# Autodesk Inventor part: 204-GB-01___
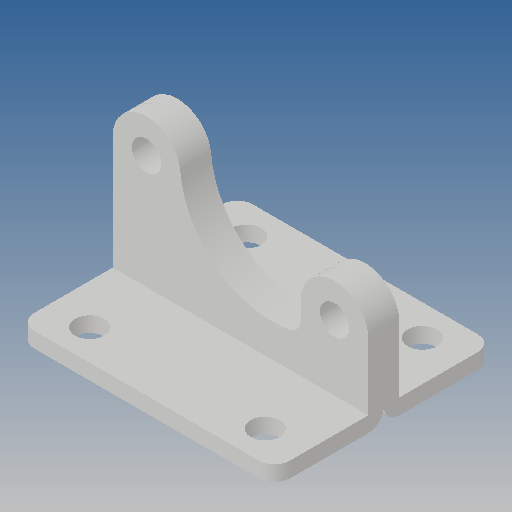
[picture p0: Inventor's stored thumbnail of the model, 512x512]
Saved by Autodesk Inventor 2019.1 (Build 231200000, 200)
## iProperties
Created: 2010-06
Part Number: 204-GB-01___
Material: Ogólny
Document SubType Name: Modeling
Designer: CADENGINEERING4
Density: 1 g/cm^3
Appearance: Domyślna
Author: CADENGINEERING4
Revision Number: ANY
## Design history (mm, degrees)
feature "NONE"
feature "NONE:1"
node "Bryła1"
node "Bryła2"
